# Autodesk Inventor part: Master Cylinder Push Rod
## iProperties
Shininess: 41.0
Angle Display Precision: 2
Document Length Units: 11269
Document Angle Units: 11279
Document Time Units: 11290
Document Mass Units: 11283
Document Length Units Precision: 3
Document Angle Units Precision: 2
Compacted: True
Created: 2001-08
Part Number: Master Cylinder Push Rod
Document SubType Name: Modeling
Designer: Martin Budgell
Density: 0.0
Volumn: 0.0
Area: 0.0
PropertySet Name: Model Information
Control State: 0
Master: False
Checked Out: False
Author: Martin Budgell
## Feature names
1. Extrusion1
2. Fillet1
